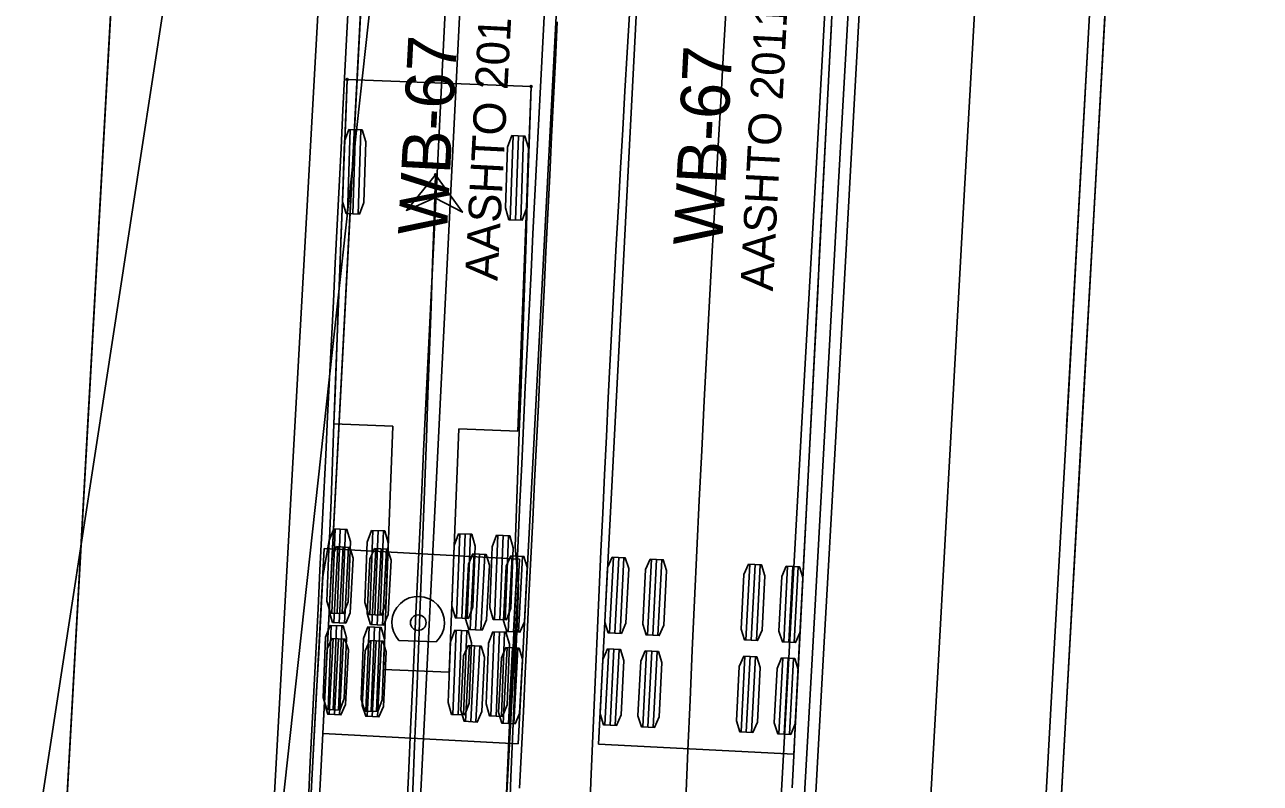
# Model space of a CAD drawing. Extents: x -70 to 701944, y -4 to 666871.
# Drawn here: x 664396.7 to 664450.5, y 657185.7 to 657218.7 of the extents above; entities that cross this region are included whole.
import ezdxf

# ---------------------------------------------------------------- set-up
doc = ezdxf.new("R2010")
doc.units = 0
for name, color, linetype in [('R_Horz Alg', 7, 'Continuous'), ('R_No Plot', 7, 'Continuous'), ('R_Proposed Road', 7, 'Continuous'), ('R_Striping', 7, 'Continuous'), ('T_Indications', 7, 'Continuous'), ('T_Vehicle Path Lt Minor', 7, 'Continuous'), ('T_Vehicle Path Rt', 7, 'Continuous')]:
    doc.layers.add(name, color=color, linetype=linetype)

msp = doc.modelspace()

# ---------------------------------------------------------------- linework, layer by layer
at = {"layer": 'R_Horz Alg'}
msp.add_line((664392.828, 657081.683), (664417.37, 657522.584), dxfattribs=at)
at = {"layer": 'R_No Plot'}
for p, q in [((664414.231, 657304.256), (664408.595, 657203.009)), ((664408.595, 657203.009), (664401.814, 657081.183))]:
    msp.add_line(p, q, dxfattribs=at)
for points in [[(664342.835, 657164.173), (664346.837, 657236.055), (664401.253, 657233.033), (664397.251, 657161.144)], [(664401.253, 657233.033), (664444.353, 657230.639), (664440.351, 657158.745), (664397.251, 657161.144)]]:
    msp.add_lwpolyline(points, close=True, dxfattribs=at)
at = {"layer": 'R_Proposed Road'}
for points in [[(664429.426, 657181.387), (664429.982, 657191.371), (664430.537, 657201.356), (664431.093, 657211.34), (664431.649, 657221.325), (664432.205, 657231.31), (664432.761, 657241.294), (664433.316, 657251.279), (664433.385, 657252.517), (664433.872, 657261.263), (664434.428, 657271.248), (664434.984, 657281.232), (664435.539, 657291.217), (664436.095, 657301.201), (664436.651, 657311.186), (664437.207, 657321.17), (664437.763, 657331.155), (664438.318, 657341.14)], [(664430.434, 657181.331), (664430.99, 657191.315), (664431.546, 657201.3), (664432.102, 657211.284), (664432.657, 657221.269), (664433.213, 657231.253), (664433.769, 657241.238), (664434.325, 657251.223), (664434.394, 657252.461), (664434.881, 657261.207), (664435.436, 657271.192), (664435.992, 657281.176), (664436.548, 657291.161), (664437.104, 657301.145), (664437.659, 657311.13), (664438.215, 657321.114), (664438.771, 657331.099), (664439.327, 657341.083)], [(664430.924, 657181.303), (664431.479, 657191.288), (664432.035, 657201.273), (664432.591, 657211.257), (664433.147, 657221.242), (664433.702, 657231.226), (664434.258, 657241.211), (664434.814, 657251.195), (664434.883, 657252.434), (664435.37, 657261.18), (664435.926, 657271.164), (664436.481, 657281.149), (664437.037, 657291.133), (664437.593, 657301.118), (664438.149, 657311.103), (664438.704, 657321.087), (664439.26, 657331.072), (664439.816, 657341.056)], [(664435.916, 657181.026), (664436.472, 657191.01), (664437.027, 657200.995), (664437.583, 657210.979), (664438.139, 657220.964), (664438.695, 657230.948), (664439.25, 657240.933), (664439.806, 657250.917), (664439.875, 657252.156), (664440.362, 657260.902), (664440.918, 657270.886), (664441.474, 657280.871), (664442.029, 657290.856), (664442.585, 657300.84), (664443.141, 657310.825), (664443.697, 657320.809), (664444.253, 657330.794), (664444.808, 657340.778)], [(664440.908, 657180.748), (664441.464, 657190.732), (664442.02, 657200.717), (664442.575, 657210.701), (664443.131, 657220.686), (664443.687, 657230.67), (664444.243, 657240.655), (664444.799, 657250.64), (664444.868, 657251.878), (664445.354, 657260.624), (664445.91, 657270.609), (664446.466, 657280.593), (664447.022, 657290.578), (664447.577, 657300.562), (664448.133, 657310.547), (664448.689, 657320.531), (664449.245, 657330.516), (664449.801, 657340.5)], [(664441.574, 657180.711), (664442.129, 657190.695), (664442.685, 657200.68), (664443.241, 657210.664), (664443.797, 657220.649), (664444.353, 657230.633), (664444.908, 657240.618), (664445.464, 657250.602), (664445.533, 657251.841), (664446.02, 657260.587), (664446.576, 657270.572), (664447.132, 657280.556), (664447.687, 657290.541), (664448.243, 657300.525), (664448.799, 657310.51), (664449.355, 657320.494), (664449.91, 657330.479), (664450.466, 657340.463)]]:
    msp.add_lwpolyline(points, dxfattribs=at)
at = {"layer": 'R_Striping'}
msp.add_line((664407.182, 657177.617), (664433.907, 657421.509), dxfattribs=at)
msp.add_lwpolyline([(664397.226, 657183.179), (664398.749, 657193.11), (664400.272, 657203.041), (664401.795, 657212.971), (664403.318, 657222.902), (664404.841, 657232.833), (664406.364, 657242.763), (664407.887, 657252.694), (664408.076, 657253.926), (664409.41, 657262.625), (664410.933, 657272.556), (664412.456, 657282.486), (664413.979, 657292.417), (664415.502, 657302.348), (664417.025, 657312.278), (664418.548, 657322.209), (664420.071, 657332.14), (664421.594, 657342.07)], dxfattribs=at)
at = {"layer": 'T_Indications'}
msp.add_line((664447.679, 657302.394), (664442.044, 657201.147), dxfattribs=at)
at = {"layer": 'T_Vehicle Path Lt Minor'}
for p, q in [((664410.765, 657216.282), (664410.184, 657201.293)), ((664418.759, 657215.972), (664410.765, 657216.282)), ((664410.765, 657216.282), (664410.765, 657216.282)), ((664418.178, 657200.984), (664418.759, 657215.972)), ((664410.899, 657214.105), (664410.778, 657210.44)), ((664411.128, 657214.097), (664411.007, 657210.432)), ((664411.357, 657214.089), (664411.236, 657210.425)), ((664417.977, 657213.836), (664417.856, 657210.171)), ((664418.207, 657213.828), (664418.085, 657210.163)), ((664418.436, 657213.82), (664418.314, 657210.156)), ((664410.184, 657201.293), (664412.749, 657201.194)), ((664412.749, 657201.194), (664412.338, 657190.602)), ((664415.203, 657190.491), (664415.613, 657201.083)), ((664415.613, 657201.083), (664418.178, 657200.984)), ((664410.236, 657196.721), (664410.094, 657193.057)), ((664410.465, 657196.712), (664410.323, 657193.048)), ((664410.694, 657196.703), (664410.552, 657193.039)), ((664411.885, 657196.657), (664411.743, 657192.993)), ((664412.114, 657196.648), (664411.972, 657192.984)), ((664412.343, 657196.639), (664412.201, 657192.976)), ((664415.665, 657196.511), (664415.524, 657192.847)), ((664415.894, 657196.502), (664415.753, 657192.838)), ((664416.123, 657196.493), (664415.982, 657192.829)), ((664417.314, 657196.447), (664417.172, 657192.783)), ((664417.543, 657196.438), (664417.401, 657192.774)), ((664417.772, 657196.429), (664417.63, 657192.765)), ((664409.77, 657195.869), (664406.913, 657142.947)), ((664418.257, 657195.411), (664409.77, 657195.869)), ((664409.77, 657195.869), (664409.77, 657195.869)), ((664415.401, 657142.488), (664418.257, 657195.411)), ((664410.074, 657192.524), (664409.932, 657188.86)), ((664410.303, 657192.515), (664410.161, 657188.851)), ((664410.532, 657192.507), (664410.39, 657188.843)), ((664411.722, 657192.46), (664411.58, 657188.796)), ((664411.951, 657192.452), (664411.809, 657188.788)), ((664412.18, 657192.443), (664412.038, 657188.779)), ((664415.503, 657192.314), (664415.361, 657188.65)), ((664415.732, 657192.305), (664415.59, 657188.641)), ((664415.961, 657192.296), (664415.819, 657188.632)), ((664417.152, 657192.25), (664417.01, 657188.586)), ((664417.381, 657192.241), (664417.239, 657188.577)), ((664417.61, 657192.232), (664417.468, 657188.568)), ((664413.013, 657191.869), (664414.628, 657191.806)), ((664412.338, 657190.602), (664415.203, 657190.491))]:
    msp.add_line(p, q, dxfattribs=at)
for points in [[(664409.077, 657184.919), (664409.161, 657186.588), (664409.244, 657188.257), (664409.328, 657189.926), (664409.411, 657191.595), (664409.495, 657193.264), (664409.578, 657194.933), (664409.662, 657196.602), (664409.745, 657198.271), (664409.829, 657199.94), (664409.912, 657201.609), (664409.996, 657203.278), (664410.079, 657204.947), (664410.163, 657206.616), (664410.246, 657208.286), (664410.33, 657209.955), (664410.414, 657211.624), (664410.497, 657213.293), (664410.581, 657214.962), (664410.664, 657216.631), (664410.748, 657218.3), (664410.831, 657219.969)], [(664417.663, 657184.549), (664417.738, 657186.217), (664417.813, 657187.885), (664417.889, 657189.552), (664417.965, 657191.22), (664418.042, 657192.888), (664418.119, 657194.556), (664418.196, 657196.223), (664418.274, 657197.891), (664418.352, 657199.558), (664418.43, 657201.226), (664418.509, 657202.894), (664418.589, 657204.561), (664418.671, 657206.229), (664418.757, 657207.896), (664418.843, 657209.563), (664418.929, 657211.23), (664419.015, 657212.897), (664419.102, 657214.564), (664419.188, 657216.232), (664419.275, 657217.899), (664419.361, 657219.566)], [(664409.166, 657184.678), (664409.255, 657186.341), (664409.345, 657188.004), (664409.435, 657189.667), (664409.525, 657191.33), (664409.615, 657192.993), (664409.704, 657194.656), (664410, 657196.308), (664410.062, 657197.973), (664410.124, 657199.637), (664410.184, 657201.302), (664410.249, 657202.966), (664410.313, 657204.631), (664410.378, 657206.295), (664410.442, 657207.96), (664410.507, 657209.624), (664410.571, 657211.289), (664410.636, 657212.953), (664410.7, 657214.618), (664410.765, 657216.282)], [(664417.817, 657184.259), (664417.885, 657185.927), (664417.952, 657187.595), (664418.018, 657189.264), (664418.083, 657190.932), (664418.148, 657192.601), (664418.212, 657194.269), (664418.062, 657195.949), (664418.124, 657197.618), (664418.186, 657199.286), (664418.247, 657200.955), (664418.307, 657202.623), (664418.366, 657204.292), (664418.425, 657205.96), (664418.482, 657207.629), (664418.539, 657209.298), (664418.595, 657210.966), (664418.651, 657212.635), (664418.705, 657214.304), (664418.759, 657215.972)]]:
    msp.add_lwpolyline(points, dxfattribs=at)
for points in [[(664410.842, 657214.106), (664411.414, 657214.088), (664411.569, 657213.569), (664411.482, 657210.93), (664411.293, 657210.423), (664410.721, 657210.442), (664410.566, 657210.961), (664410.653, 657213.599)], [(664417.921, 657213.837), (664418.492, 657213.819), (664418.648, 657213.3), (664418.56, 657210.661), (664418.371, 657210.154), (664417.799, 657210.173), (664417.644, 657210.691), (664417.731, 657213.33)], [(664414.607, 657212.13), (664413.338, 657210.585), (664414.574, 657211.131), (664415.771, 657210.504)], [(664410.179, 657196.723), (664410.751, 657196.701), (664410.903, 657196.182), (664410.801, 657193.544), (664410.609, 657193.037), (664410.037, 657193.059), (664409.885, 657193.579), (664409.987, 657196.217)], [(664411.828, 657196.659), (664412.4, 657196.637), (664412.552, 657196.118), (664412.45, 657193.48), (664412.258, 657192.973), (664411.686, 657192.996), (664411.534, 657193.515), (664411.636, 657196.153)], [(664415.609, 657196.513), (664416.18, 657196.491), (664416.333, 657195.971), (664416.23, 657193.333), (664416.038, 657192.827), (664415.467, 657192.849), (664415.314, 657193.369), (664415.417, 657196.007)], [(664417.257, 657196.449), (664417.829, 657196.427), (664417.981, 657195.907), (664417.879, 657193.269), (664417.687, 657192.763), (664417.115, 657192.785), (664416.963, 657193.305), (664417.065, 657195.943)], [(664410.017, 657192.526), (664410.588, 657192.504), (664410.741, 657191.985), (664410.639, 657189.347), (664410.446, 657188.84), (664409.875, 657188.863), (664409.723, 657189.382), (664409.825, 657192.02)], [(664411.666, 657192.463), (664412.237, 657192.44), (664412.389, 657191.921), (664412.287, 657189.283), (664412.095, 657188.777), (664411.524, 657188.799), (664411.371, 657189.318), (664411.474, 657191.956)], [(664415.446, 657192.316), (664416.018, 657192.294), (664416.17, 657191.774), (664416.068, 657189.136), (664415.876, 657188.63), (664415.304, 657188.652), (664415.152, 657189.172), (664415.254, 657191.81)], [(664417.095, 657192.252), (664417.666, 657192.23), (664417.819, 657191.71), (664417.717, 657189.072), (664417.524, 657188.566), (664416.953, 657188.588), (664416.801, 657189.108), (664416.903, 657191.746)]]:
    msp.add_lwpolyline(points, close=True, dxfattribs=at)
for centre, radius in [((664410.765, 657216.282), 0.0417), ((664418.759, 657215.972), 0.0417), ((664414.607, 657212.13), 0.0417), ((664413.852, 657192.645), 0.34)]:
    msp.add_circle(centre, radius, dxfattribs=at)
for centre, radius, start, end in [((671821.876, 656847.141), 7416.192, 176.7069339, 177.8734926), ((660944.556, 657326.883), 3471.947, 356.085934, 358.105948), ((664413.852, 657192.645), 1.143, 312.7814, 222.7814)]:
    msp.add_arc(centre, radius, start, end, dxfattribs=at)
at = {"layer": 'T_Vehicle Path Rt'}
for p, q in [((664410.543, 657116.325), (664417.532, 657257.008)), ((664412.477, 657240.75), (664409.705, 657187.822)), ((664418.194, 657187.378), (664420.966, 657240.305)), ((664424.424, 657240.294), (664421.692, 657187.365)), ((664430.181, 657186.926), (664432.913, 657239.856)), ((664410.36, 657195.949), (664410.188, 657192.654)), ((664410.589, 657195.937), (664410.417, 657192.642)), ((664410.818, 657195.925), (664410.646, 657192.63)), ((664412.008, 657195.863), (664411.836, 657192.568)), ((664412.237, 657195.851), (664412.064, 657192.556)), ((664412.466, 657195.839), (664412.293, 657192.544)), ((664416.286, 657195.639), (664416.113, 657192.343)), ((664416.515, 657195.627), (664416.342, 657192.332)), ((664416.743, 657195.615), (664416.571, 657192.32)), ((664417.933, 657195.553), (664417.761, 657192.257)), ((664418.162, 657195.541), (664417.99, 657192.245)), ((664418.391, 657195.529), (664418.219, 657192.233)), ((664422.341, 657195.492), (664422.171, 657192.196)), ((664422.57, 657195.48), (664422.4, 657192.184)), ((664422.799, 657195.468), (664422.629, 657192.173)), ((664423.989, 657195.407), (664423.819, 657192.111)), ((664424.218, 657195.395), (664424.048, 657192.099)), ((664424.447, 657195.383), (664424.277, 657192.088)), ((664428.267, 657195.186), (664428.097, 657191.89)), ((664428.496, 657195.174), (664428.326, 657191.879)), ((664428.724, 657195.162), (664428.554, 657191.867)), ((664429.915, 657195.101), (664429.744, 657191.805)), ((664430.143, 657195.089), (664429.973, 657191.794)), ((664430.372, 657195.077), (664430.202, 657191.782)), ((664410.151, 657191.955), (664409.979, 657188.659)), ((664410.38, 657191.943), (664410.207, 657188.647)), ((664410.609, 657191.931), (664410.436, 657188.635)), ((664411.799, 657191.868), (664411.626, 657188.573)), ((664412.028, 657191.856), (664411.855, 657188.561)), ((664412.257, 657191.845), (664412.084, 657188.549)), ((664416.076, 657191.644), (664415.904, 657188.349)), ((664416.305, 657191.632), (664416.133, 657188.337)), ((664416.534, 657191.62), (664416.362, 657188.325)), ((664417.724, 657191.558), (664417.552, 657188.263)), ((664417.953, 657191.546), (664417.78, 657188.251)), ((664418.182, 657191.534), (664418.009, 657188.239)), ((664422.135, 657191.497), (664421.965, 657188.202)), ((664422.364, 657191.485), (664422.194, 657188.19)), ((664422.593, 657191.474), (664422.423, 657188.178)), ((664423.783, 657191.412), (664423.613, 657188.117)), ((664424.012, 657191.4), (664423.842, 657188.105)), ((664424.241, 657191.389), (664424.071, 657188.093)), ((664428.061, 657191.191), (664427.89, 657187.896)), ((664428.289, 657191.18), (664428.119, 657187.884)), ((664428.518, 657191.168), (664428.348, 657187.872)), ((664429.708, 657191.106), (664429.538, 657187.811)), ((664429.937, 657191.095), (664429.767, 657187.799)), ((664430.166, 657191.083), (664429.996, 657187.787)), ((664409.705, 657187.822), (664418.194, 657187.378)), ((664421.692, 657187.365), (664430.181, 657186.926))]:
    msp.add_line(p, q, dxfattribs=at)
for points in [[(664409.514, 657184.214), (664409.602, 657185.881), (664409.69, 657187.547), (664409.778, 657189.214), (664409.865, 657190.88), (664409.953, 657192.547), (664410.04, 657194.214), (664410.127, 657195.88), (664410.215, 657197.547), (664410.302, 657199.213), (664410.389, 657200.88), (664410.476, 657202.546), (664410.564, 657204.213), (664410.651, 657205.88), (664410.738, 657207.546), (664410.826, 657209.213), (664410.913, 657210.879), (664411, 657212.546), (664411.087, 657214.213), (664411.175, 657215.879), (664411.262, 657217.546), (664411.349, 657219.212)], [(664421.293, 657184.047), (664421.36, 657185.718), (664421.429, 657187.388), (664421.499, 657189.059), (664421.57, 657190.729), (664421.644, 657192.4), (664421.719, 657194.07), (664421.795, 657195.74), (664421.874, 657197.41), (664421.953, 657199.081), (664422.035, 657200.751), (664422.118, 657202.421), (664422.202, 657204.091), (664422.289, 657205.76), (664422.376, 657207.43), (664422.466, 657209.1), (664422.557, 657210.769), (664422.649, 657212.439), (664422.743, 657214.108), (664422.839, 657215.778), (664422.936, 657217.447), (664423.035, 657219.116)], [(664418.259, 657185.447), (664418.341, 657187.114), (664418.423, 657188.781), (664418.505, 657190.448), (664418.587, 657192.115), (664418.669, 657193.782), (664418.751, 657195.449), (664418.833, 657197.116), (664418.915, 657198.783), (664418.997, 657200.449), (664419.079, 657202.116), (664419.161, 657203.783), (664419.243, 657205.45), (664419.325, 657207.117), (664419.407, 657208.784), (664419.489, 657210.451), (664419.572, 657212.118), (664419.654, 657213.785), (664419.736, 657215.452), (664419.819, 657217.119), (664419.901, 657218.786)], [(664430.112, 657185.46), (664430.195, 657187.122), (664430.278, 657188.784), (664430.363, 657190.447), (664430.449, 657192.109), (664430.534, 657193.771), (664430.62, 657195.433), (664430.706, 657197.095), (664430.792, 657198.757), (664430.877, 657200.42), (664430.963, 657202.082), (664431.049, 657203.744), (664431.135, 657205.406), (664431.221, 657207.068), (664431.306, 657208.73), (664431.392, 657210.392), (664431.478, 657212.054), (664431.564, 657213.716), (664431.649, 657215.378), (664431.735, 657217.04), (664431.821, 657218.702)]]:
    msp.add_lwpolyline(points, dxfattribs=at)
for points in [[(664410.304, 657195.952), (664410.875, 657195.922), (664411.023, 657195.452), (664410.899, 657193.079), (664410.702, 657192.627), (664410.131, 657192.657), (664409.983, 657193.127), (664410.107, 657195.5)], [(664411.951, 657195.866), (664412.523, 657195.836), (664412.671, 657195.366), (664412.546, 657192.993), (664412.35, 657192.541), (664411.779, 657192.57), (664411.631, 657193.041), (664411.755, 657195.414)], [(664416.229, 657195.642), (664416.8, 657195.612), (664416.948, 657195.142), (664416.824, 657192.769), (664416.628, 657192.317), (664416.056, 657192.346), (664415.908, 657192.817), (664416.033, 657195.19)], [(664417.877, 657195.556), (664418.448, 657195.526), (664418.596, 657195.055), (664418.472, 657192.683), (664418.275, 657192.23), (664417.704, 657192.26), (664417.556, 657192.731), (664417.68, 657195.103)], [(664422.285, 657195.495), (664422.856, 657195.465), (664423.004, 657194.995), (664422.882, 657192.622), (664422.686, 657192.17), (664422.114, 657192.199), (664421.966, 657192.669), (664422.089, 657195.042)], [(664423.932, 657195.41), (664424.504, 657195.38), (664424.652, 657194.91), (664424.529, 657192.537), (664424.333, 657192.085), (664423.762, 657192.114), (664423.614, 657192.584), (664423.736, 657194.957)], [(664428.21, 657195.189), (664428.781, 657195.16), (664428.93, 657194.689), (664428.807, 657192.316), (664428.611, 657191.864), (664428.04, 657191.893), (664427.892, 657192.364), (664428.014, 657194.736)], [(664429.858, 657195.104), (664430.429, 657195.074), (664430.577, 657194.604), (664430.455, 657192.231), (664430.259, 657191.779), (664429.688, 657191.808), (664429.539, 657192.279), (664429.662, 657194.651)], [(664410.094, 657191.958), (664410.666, 657191.928), (664410.814, 657191.457), (664410.689, 657189.085), (664410.493, 657188.632), (664409.922, 657188.662), (664409.774, 657189.133), (664409.898, 657191.505)], [(664411.742, 657191.871), (664412.313, 657191.842), (664412.461, 657191.371), (664412.337, 657188.998), (664412.141, 657188.546), (664411.57, 657188.576), (664411.422, 657189.046), (664411.546, 657191.419)], [(664416.02, 657191.647), (664416.591, 657191.618), (664416.739, 657191.147), (664416.615, 657188.774), (664416.418, 657188.322), (664415.847, 657188.352), (664415.699, 657188.822), (664415.823, 657191.195)], [(664417.667, 657191.561), (664418.239, 657191.531), (664418.387, 657191.061), (664418.262, 657188.688), (664418.066, 657188.236), (664417.495, 657188.266), (664417.347, 657188.736), (664417.471, 657191.109)], [(664422.078, 657191.5), (664422.65, 657191.471), (664422.798, 657191), (664422.675, 657188.628), (664422.48, 657188.175), (664421.908, 657188.205), (664421.76, 657188.675), (664421.882, 657191.048)], [(664423.726, 657191.415), (664424.297, 657191.386), (664424.446, 657190.915), (664424.323, 657188.542), (664424.127, 657188.09), (664423.556, 657188.119), (664423.408, 657188.59), (664423.53, 657190.963)], [(664428.004, 657191.194), (664428.575, 657191.165), (664428.723, 657190.695), (664428.601, 657188.322), (664428.405, 657187.869), (664427.834, 657187.899), (664427.685, 657188.369), (664427.808, 657190.742)], [(664429.652, 657191.109), (664430.223, 657191.08), (664430.371, 657190.61), (664430.249, 657188.237), (664430.053, 657187.784), (664429.482, 657187.814), (664429.333, 657188.284), (664429.456, 657190.657)]]:
    msp.add_lwpolyline(points, close=True, dxfattribs=at)
msp.add_arc((666230.268, 657110.052), 1806.333, 175.348679, 179.761956, dxfattribs=at)

# ---------------------------------------------------------------- texts
for s, height, rotation, p in [('AASHTO 2011 (US)', 1.41667, 87.002, (664417.297, 657207.502)), ('AASHTO 2011 (US)', 1.41667, 87.0457, (664429.269, 657207.05)), ('WB-67', 2.125, 87.002, (664415.094, 657209.452)), ('WB-67', 2.125, 87.0457, (664427.065, 657208.998))]:
    msp.add_text(s, height=height, rotation=rotation, dxfattribs=at).set_placement(p)

doc.saveas('drawing.dxf')
